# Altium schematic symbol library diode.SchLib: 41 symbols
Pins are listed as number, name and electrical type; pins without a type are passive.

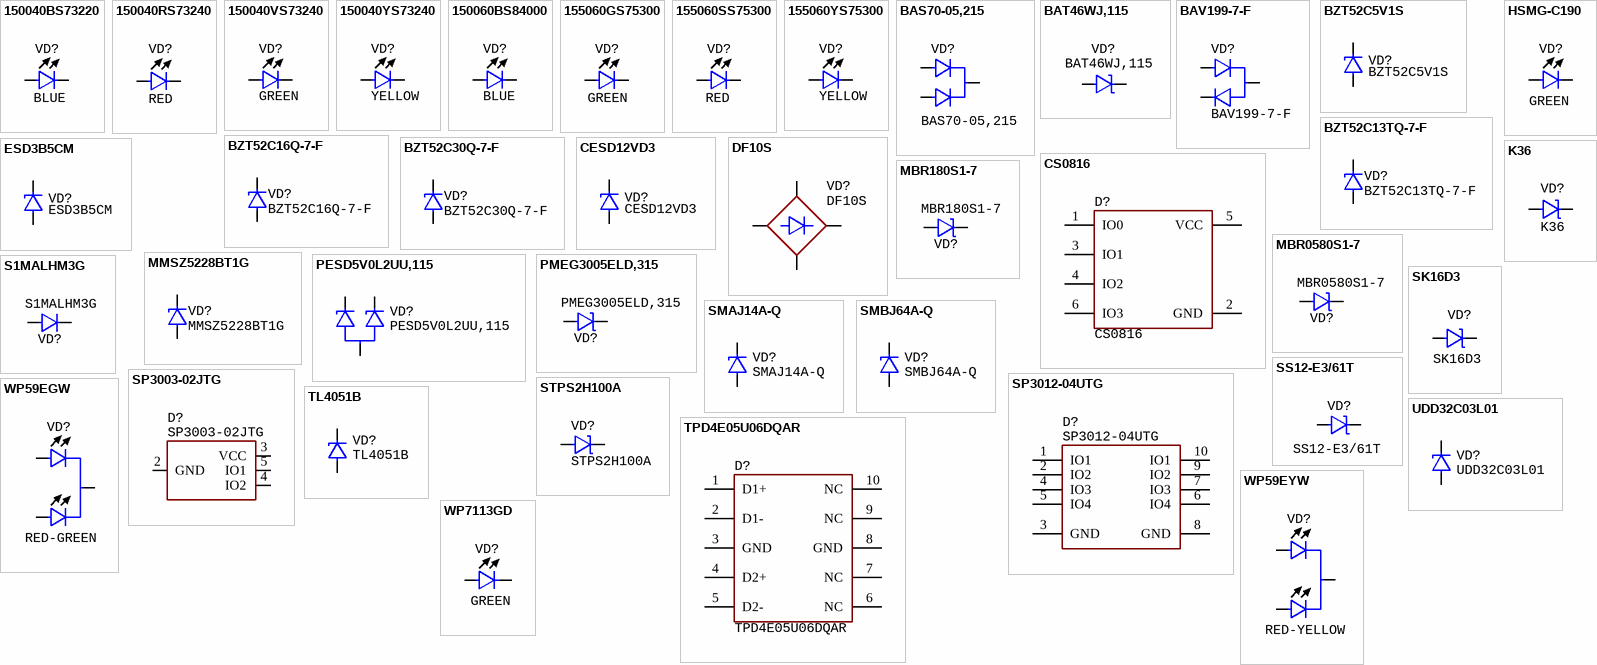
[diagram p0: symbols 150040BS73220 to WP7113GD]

## 150040BS73220
designator VD?  Color: BLUE  (hidden comment: 150040BS73220)
LED, Blue, case 0402, 3.2V, 30mA, -40...+85°C; Manufacturer: Wurth; Manufacturer: Wurth Electronics
footprint LED: 0402B
pins: 1, 2

## 150040RS73240
designator VD?  Color: RED  (hidden comment: 150040RS73240)
LED, Red, case 0402, 2V, 30mA, -40...+85°C; Manufacturer: Wurth; Manufacturer: Wurth Electronics
footprint LED: 0402R
pins: 1, 2

## 150040VS73240
designator VD?  Color: GREEN  (hidden comment: 150040VS73240)
LED, Green, case 0402, 2V, 30mA, -40...+85°C; Manufacturer: Wurth; Manufacturer: Wurth Electronics
footprint LED: 0402G
pins: 1, 2

## 150040YS73240
designator VD?  Color: YELLOW  (hidden comment: 150040YS73240)
LED, Yellow, case 0402, 2V, 30mA, -40...+85°C; Manufacturer: Wurth; Manufacturer: Wurth Electronics
footprint LED: 0402Y
pins: 1, 2

## 150060BS84000
designator VD?  Color: BLUE  (hidden comment: 150060BS84000)
LED, Blue, case 0603, 3.2V, 30mA, -40...+85°C; Manufacturer: Wurth; Manufacturer: Wurth Electronics
footprint LED: 0603B
pins: 1, 2

## 155060GS75300
designator VD?  Color: GREEN  (hidden comment: 155060GS75300)
LED, Green, case 0603, 3.2V, 30mA, -40...+85°C; Manufacturer: Wurth; Manufacturer: Wurth Electronics
footprint LED: 0603G
pins: 1, 2

## 155060SS75300
designator VD?  Color: RED  (hidden comment: 155060SS75300)
LED, Red, case 0603, 2V, 20mA, -40...+85°C; Manufacturer: Wurth; Manufacturer: Wurth Electronics
footprint LED: 0603R
pins: 1, 2

## 155060YS75300
designator VD?  Color: YELLOW  (hidden comment: 155060YS75300)
LED, Yellow, case 0603, 2.0V, 20mA, -40...+85°C; Manufacturer: Wurth; Manufacturer: Wurth Electronics
footprint LED: 0603Y
pins: 1, 2

## BAS70-05,215
designator VD?
Dual fast, 70V, 70mA, 1V, SOT-23, -65...+150°C; Manufacturer: STMicroelectronics; Manufacturer: Nexperia
footprint SOT23
pins: 1, 2, 3

## BAT46WJ,115
designator VD?
Schottky, 100V, 250mA, SOD-323, 71mV, -55...+175°C; Manufacturer: Nexperia
footprint DIODE: SOD323
pins: 1, 2

## BAV199-7-F
designator VD?
Dual fast, 85V, 160mA, 0.25W, SOT-23, -65...+150°C; Manufacturer: Diodes Incorporated; Manufacturer: Diodes
footprint SOT23
pins: 1, 2, 3

## BZT52C5V1S
designator VD?
Zener, 5.1V, SOD-323, 900mV, -55...+150°C; Manufacturer: Jiangsu Tech
footprint DIODE: SOD323
pins: 1, 2

## BZT52C13TQ-7-F
designator VD?
Zener, 13V, 30 Ohms, 900mV, SOD-523, -55...+150°C; Manufacturer: Diodes Incorporated; Manufacturer: Diodes
footprint SOD523
pins: 1, 2

## BZT52C16Q-7-F
designator VD?
Zener, 16V, 40 Ohm, SOD-123, 900mV, -55...+150°C; Manufacturer: Diodes
footprint SOD123
pins: 1, 2

## BZT52C30Q-7-F
designator VD?
Zener, 30V, 80 Ohm, SOD-123, 900mV, -55...+150°C; Manufacturer: Diodes
footprint SOD123
pins: 1, 2

## CESD12VD3
designator VD?
TVS, 13.3V, 9A, SOD-323, 350W, -55...+150°C; Manufacturer: Jiangsu Technology
footprint DIODE: SOD323
pins: 1, 2

## CS0816
designator D?
TVS, 5.5V, USB, 0.7pF, SOT23-6, -55...+150°C; Manufacturer: Silergy
footprint SOT23-6 (pitch 0.95 mm)
pins: 1 IO0, 2 GND, 3 IO1, 4 IO2, 5 VCC, 6 IO3

## DF10S
designator VD?
Bridge, 1-ph, 1000V, 1A, -55...+150°C; Manufacturer: Fairchild
footprint DIODE: DF10S
pins: 1, 2, 3, 4

## ESD3B5CM
designator VD?
TVS, 6V, 5A, SOD-323, 350W, -55...+150°C; Manufacturer: MDD
footprint DIODE: SOD323
pins: 1, 2

## HSMG-C190
designator VD?  Color: GREEN  (hidden comment: HSMG-C190)
LED, Green, case 0603, 2.2V, 20mA, -40...+85°C; Manufacturer: Broadcom / Avago; Manufacturer: Broadcom Avago
footprint LED: 0603G
pins: 1, 2

## K36
designator VD?
Schottky, 60V, 3A, SOD-123FL, 700mV, -55...+175°C; Manufacturer: Goodwork
footprint SOD123
pins: 1, 2

## MBR180S1-7
designator VD?
Schottky, 80V, 1A, SOD-123, 800mV, -55...+175°C; Manufacturer: Diodes
footprint SOD123
pins: 1, 2

## MBR0580S1-7
designator VD?
Schottky, 80V, 500mA, SOD-123, 800mV, -55...+175°C; Manufacturer: Diodes Incorporated; Manufacturer: Diodes
footprint SOD123
pins: 1, 2

## MMSZ5228BT1G
designator VD?
TVS, 3.9V, 23 Ohm, SOD-123, 900mV, -55...+150°C; Manufacturer: ON Semiconductor
footprint SOD123
pins: 1, 2

## PESD5V0L2UU,115
designator VD?
TVS dual, 5V, 20W peak, 38 pF, 6.5, SC-70, -55...+150°C; Manufacturer: Nexperia
footprint SC-70
pins: 1, 2, 3

## PMEG3005ELD,315
designator VD?
Schottky, 30V, 3A, DFN-1006, 450mV, -65...+150°C; Manufacturer: Nexperia; Manufacturer: Nexperia USA
footprint DFN-1006
pins: 1, 2

## S1MALHM3G
designator VD?
Ultra-fast, 1000V, 1A, SMA, 960mV, -55...+155°C; Manufacturer: Taiwan Semiconductor
footprint SMA
pins: 1, 2

## SK16D3
designator VD?
Schottky, 60V, 1A, SOD-323, 700mV, -55...+175°C; Manufacturer: Fuxin Semiconductor
footprint DIODE: SOD323
pins: 1, 2

## SMAJ14A-Q
designator VD?
TVS, 14V, peak 17.2A, 400W, SMA, -55...+150°C; Manufacturer: Bourns
footprint SMA
pins: 1, 2

## SMBJ64A-Q
designator VD?
TVS, 64V, 5.9A, 600W, SMB, -65...+150°C; Manufacturer: Bourns; Manufacturer Part Number: SMBJ64A-QH
footprint SMB (DIODE)
pins: 1, 2

## SP3003-02JTG
designator D?
Protection ESD, 6V, 2 channels, 0.65 pF, 2.5A peak, SC70-5, -40...+125°C; Manufacturer: Littelfuse
footprint SC70-5
pins: 2 GND, 3 VCC, 4 IO2, 5 IO1

## SP3012-04UTG
designator D?
Protection ESD, 5V, 2 channels, 0.5 pF, 4A peak, uDFN-10, -40...+125°C; Manufacturer: Littelfuse
footprint 10-DFN (2.5x1) (3x3 mm, pitch 0.5 mm, power pad)
pins: 1 IO1, 2 IO2, 3 GND, 4 IO3, 5 IO4, 6 IO4, 7 IO3, 8 GND, 9 IO2, 10 IO1

## SS12-E3/61T
designator VD?
Schottky, 20V, 1A, SMA, 0.5V, -65...+150°C; Manufacturer: Vishay; Manufacturer: Vishay Semiconductors
footprint SMA
pins: 1, 2

## STPS2H100A
designator VD?
Schottky, 100V, 2A, SMA, 790mV, -55...+175°C; Manufacturer: STMicroelectronics
footprint SMA
pins: 1, 2

## TL4051B
designator VD?
Zener, 1.225V, 12 mA, ±0.2%, SOT-23-3, 50ppm/°C, -55...+150°C; PartNumber: TL4051B12IDBZR; Manufacturer: Texas Instruments
footprint SOT23
pins: 1, 2

## TPD4E05U06DQAR
designator D?
TVS, 4 channels, 5.5V, 5A, 40W, SMB, -40...+125°C; Manufacturer: Texas Instruments
footprint IC: TPD4E05U06DQAR
pins: 1 D1+, 2 D1-, 3 GND, 4 D2+, 5 D2-, 6 NC, 7 NC, 8 GND, 9 NC, 10 NC

## UDD32C03L01
designator VD?
TVS, 4V, 9A, SOD-323, 350W, -55...+150°C; Manufacturer: Brightking; Manufacturer: Bourns
footprint DIODE: SOD323
pins: 1, 2

## WP59EGW
designator VD?  Color: RED-GREEN  (hidden comment: WP59EGW)
LED, Red-Green, C. Cathode, case t-1 3/4, 3.2V, 30mA, -40...+85°C; PartNumber: 150040BS73220; Manufacturer: Wurth; Manufacturer: Wurth Electronics
footprint DIODE:TH T-1 3/4 (LED 5mm two color)
pins: 1, 2, 3

## WP59EYW
designator VD?  Color: RED-YELLOW  (hidden comment: WP59EYW)
LED, Red-Yellow, C. Cathode, case t-1 3/4, 3.2V, 30mA, -40...+85°C; PartNumber: 150040BS73220; Manufacturer: Wurth; Manufacturer: Wurth Electronics
footprint DIODE:TH T-1 3/4 (LED 5mm two color)
pins: 1, 2, 3

## WP7113GD
designator VD?  Color: GREEN  (hidden comment: WP7113GD)
LED, Green, case t-1 3/4, 3.2V, 30mA, -40...+85°C; PartNumber: 150040BS73220; Manufacturer: Wurth; Manufacturer: Wurth Electronics
footprint DIODE:TH T-1 3/4 2pin (LED 5mm)
pins: 1, 2

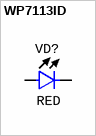
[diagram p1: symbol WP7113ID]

## WP7113ID
designator VD?  Color: RED  (hidden comment: WP7113ID)
LED, Red, case t-1 3/4, 3.2V, 30mA, -40...+85°C; PartNumber: 150040BS73220; Manufacturer: Wurth; Manufacturer: Wurth Electronics
footprint DIODE:TH T-1 3/4 2pin (LED 5mm)
pins: 1, 2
